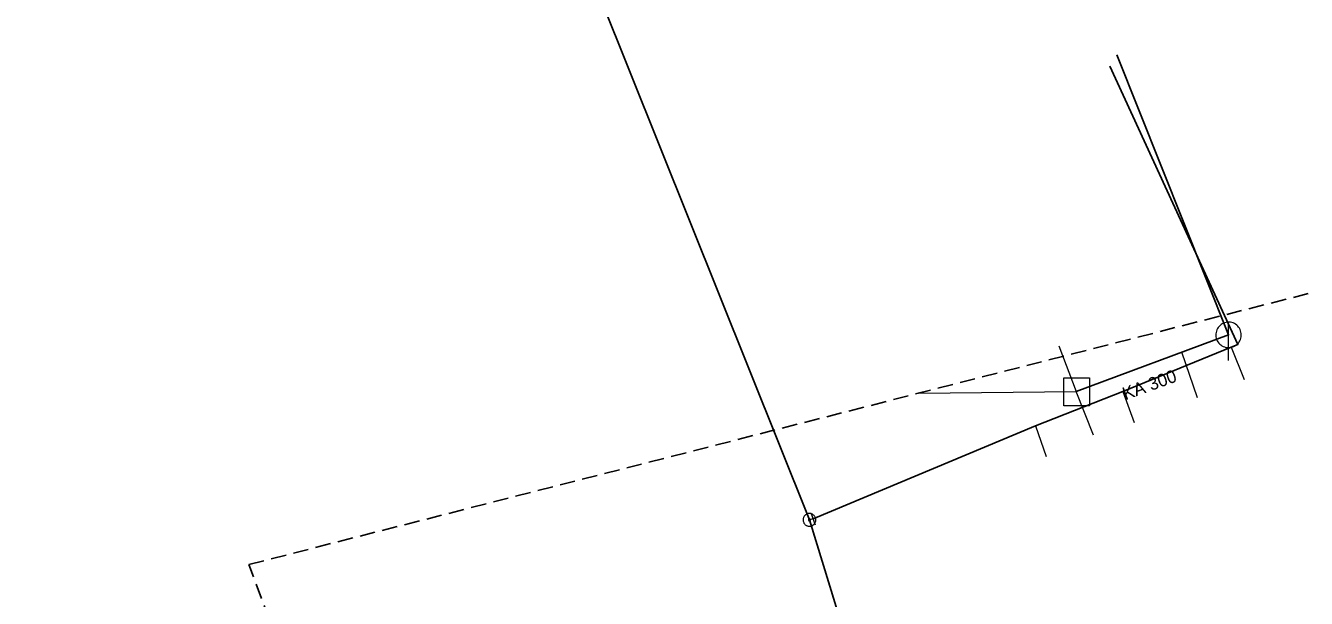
# Model space of a CAD drawing. Extents: x -690254 to -689100, y -975264 to -974703.
# Drawn here: x -689747.9 to -689647.4, y -974920.4 to -974875.5 of the extents above; entities that cross this region are included whole.
import ezdxf

# ---------------------------------------------------------------- set-up
doc = ezdxf.new("R2010")
doc.units = 0
doc.header["$LTSCALE"] = 0.4
doc.linetypes.add('MEDIUM_DASHED', pattern=[4.5, 3, -1.5])
for name, color, linetype, lineweight in [('1', 7, 'Continuous', 13), ('11', 7, 'Continuous', 13), ('13', 7, 'Continuous', 13), ('14', 7, 'Continuous', 13), ('17', 7, 'Continuous', 25), ('22', 7, 'Continuous', 13), ('34', 7, 'Continuous', 13), ('47', 7, 'Continuous', 13), ('63', 7, 'MEDIUM_DASHED', 25)]:
    doc.layers.add(name, color=color, linetype=linetype, lineweight=lineweight)

msp = doc.modelspace()

# ---------------------------------------------------------------- linework, layer by layer
at = {"layer": '11'}
for p, q in [((-689666.807, -974900.602), (-689665.436, -974904.179)), ((-689655.913, -974904.68), (-689657.145, -974901.096)), ((-689677.812, -974904.289), (-689665.436, -974904.179)), ((-689664.069, -974907.585), (-689665.436, -974904.179))]:
    msp.add_line(p, q, dxfattribs=at)
at = {"layer": '13'}
for p, q in [((-689653.268, -974900.685), (-689652.242, -974903.229)), ((-689661.782, -974904.17), (-689660.875, -974906.603)), ((-689668.633, -974906.855), (-689667.799, -974909.276))]:
    msp.add_line(p, q, dxfattribs=at)
at = {"layer": '14'}
msp.add_line((-689686.09, -974914.152), (-689686.37, -974914.237), dxfattribs=at)
at = {"layer": '14', "lineweight": 25}
msp.add_lwpolyline([(-689665.436, -974904.179), (-689653.478, -974899.732), (-689662.253, -974877.772)], dxfattribs=at)
at = {"layer": '17'}
for p, q in [((-689686.37, -974914.237), (-689718.298, -974834.599)), ((-689679.393, -974936.834), (-689686.37, -974914.237))]:
    msp.add_line(p, q, dxfattribs=at)
msp.add_lwpolyline([(-689686.09, -974914.152), (-689668.633, -974906.855), (-689661.782, -974904.17), (-689653.268, -974900.685), (-689652.74, -974900.474), (-689662.798, -974878.653)], dxfattribs=at)
at = {"layer": '22'}
msp.add_line((-689653.479, -974901.733), (-689653.478, -974898.733), dxfattribs=at)
for points in [[(-689652.479, -974899.733), (-689652.484, -974899.624), (-689652.502, -974899.516), (-689652.532, -974899.41), (-689652.572, -974899.309), (-689652.624, -974899.212), (-689652.686, -974899.122), (-689652.758, -974899.039), (-689652.838, -974898.965), (-689652.926, -974898.899), (-689653.02, -974898.844), (-689653.12, -974898.799), (-689653.225, -974898.766), (-689653.332, -974898.744), (-689653.441, -974898.734), (-689653.551, -974898.736), (-689653.659, -974898.75), (-689653.766, -974898.775), (-689653.869, -974898.812), (-689653.967, -974898.861), (-689654.059, -974898.919), (-689654.145, -974898.988), (-689654.222, -974899.065), (-689654.291, -974899.151), (-689654.35, -974899.243), (-689654.398, -974899.341), (-689654.435, -974899.444), (-689654.461, -974899.551), (-689654.475, -974899.659), (-689654.478, -974899.769), (-689654.468, -974899.878), (-689654.447, -974899.985), (-689654.413, -974900.089), (-689654.369, -974900.189), (-689654.314, -974900.284), (-689654.248, -974900.372), (-689654.174, -974900.452), (-689654.091, -974900.524), (-689654.001, -974900.586), (-689653.905, -974900.638), (-689653.803, -974900.679), (-689653.698, -974900.709), (-689653.59, -974900.727), (-689653.48, -974900.733), (-689653.371, -974900.727), (-689653.263, -974900.709), (-689653.158, -974900.68), (-689653.056, -974900.639), (-689652.959, -974900.587), (-689652.869, -974900.525), (-689652.786, -974900.454), (-689652.711, -974900.374), (-689652.646, -974900.286), (-689652.59, -974900.192), (-689652.546, -974900.092), (-689652.512, -974899.988), (-689652.49, -974899.88), (-689652.48, -974899.771)], [(-689666.416, -974903.089), (-689664.383, -974903.089), (-689664.383, -974905.282), (-689666.416, -974905.282)]]:
    msp.add_lwpolyline(points, close=True, dxfattribs=at)
at = {"layer": '34'}
msp.add_line((-689686.264, -974913.683), (-689685.916, -974914.62), dxfattribs=at)
at = {"layer": '47'}
for points in [[(-689685.896, -974914.076), (-689685.916, -974914.028), (-689685.94, -974913.981), (-689685.969, -974913.938), (-689686.002, -974913.897), (-689686.04, -974913.861), (-689686.081, -974913.828), (-689686.126, -974913.801), (-689686.172, -974913.778), (-689686.221, -974913.759), (-689686.272, -974913.746), (-689686.324, -974913.739), (-689686.376, -974913.737), (-689686.428, -974913.74), (-689686.48, -974913.749), (-689686.53, -974913.763), (-689686.578, -974913.783), (-689686.625, -974913.807), (-689686.669, -974913.837), (-689686.709, -974913.869), (-689686.745, -974913.907), (-689686.778, -974913.948), (-689686.806, -974913.993), (-689686.829, -974914.04), (-689686.848, -974914.088), (-689686.86, -974914.139), (-689686.867, -974914.191), (-689686.87, -974914.244), (-689686.866, -974914.295), (-689686.857, -974914.347), (-689686.843, -974914.397), (-689686.823, -974914.445), (-689686.799, -974914.492), (-689686.77, -974914.536), (-689686.737, -974914.576), (-689686.699, -974914.612), (-689686.659, -974914.645), (-689686.614, -974914.673), (-689686.567, -974914.696), (-689686.518, -974914.715), (-689686.467, -974914.727), (-689686.415, -974914.734), (-689686.363, -974914.737), (-689686.311, -974914.733), (-689686.259, -974914.724), (-689686.209, -974914.71), (-689686.161, -974914.69), (-689686.114, -974914.666), (-689686.071, -974914.638), (-689686.03, -974914.604), (-689685.994, -974914.566), (-689685.961, -974914.526), (-689685.934, -974914.481), (-689685.911, -974914.434), (-689685.892, -974914.385), (-689685.879, -974914.334), (-689685.872, -974914.282), (-689685.87, -974914.231), (-689685.873, -974914.178), (-689685.882, -974914.126)], [(-689686.292, -974914.21), (-689686.295, -974914.202), (-689686.299, -974914.195), (-689686.304, -974914.188), (-689686.309, -974914.181), (-689686.315, -974914.175), (-689686.322, -974914.17), (-689686.329, -974914.165), (-689686.337, -974914.161), (-689686.345, -974914.159), (-689686.353, -974914.156), (-689686.362, -974914.155), (-689686.371, -974914.155), (-689686.379, -974914.155), (-689686.387, -974914.156), (-689686.396, -974914.159), (-689686.404, -974914.162), (-689686.411, -974914.166), (-689686.418, -974914.171), (-689686.425, -974914.176), (-689686.431, -974914.182), (-689686.436, -974914.189), (-689686.441, -974914.196), (-689686.445, -974914.204), (-689686.448, -974914.213), (-689686.45, -974914.22), (-689686.451, -974914.229), (-689686.451, -974914.238), (-689686.451, -974914.246), (-689686.45, -974914.254), (-689686.447, -974914.263), (-689686.444, -974914.271), (-689686.44, -974914.278), (-689686.435, -974914.285), (-689686.43, -974914.292), (-689686.424, -974914.298), (-689686.418, -974914.303), (-689686.41, -974914.308), (-689686.402, -974914.312), (-689686.393, -974914.315), (-689686.386, -974914.317), (-689686.377, -974914.318), (-689686.368, -974914.318), (-689686.36, -974914.318), (-689686.352, -974914.317), (-689686.343, -974914.314), (-689686.335, -974914.311), (-689686.328, -974914.307), (-689686.321, -974914.302), (-689686.314, -974914.297), (-689686.308, -974914.291), (-689686.303, -974914.285), (-689686.298, -974914.277), (-689686.294, -974914.269), (-689686.292, -974914.261), (-689686.289, -974914.253), (-689686.288, -974914.244), (-689686.288, -974914.235), (-689686.288, -974914.227), (-689686.289, -974914.219)]]:
    msp.add_lwpolyline(points, close=True, dxfattribs=at)
at = {"layer": '63'}
msp.add_lwpolyline([(-690175.832, -975238.167), (-690201.511, -975156.663), (-690201.511, -975156.663), (-689696.859, -975008.171), (-689696.859, -975008.171), (-689730.354, -974917.735), (-689730.354, -974917.735), (-689127.452, -974763.66), (-689127.452, -974763.66), (-689118.52, -974838.465), (-689118.52, -974838.465), (-689624.288, -974970.21), (-689624.288, -974970.21), (-689593.026, -975070.694), (-689593.026, -975070.694)], close=True, dxfattribs=at)

# ---------------------------------------------------------------- texts
at = {"layer": '1'}
msp.add_text('KA 300', height=1, rotation=20, dxfattribs=at).set_placement((-689661.577, -974904.862))

doc.saveas('drawing.dxf')
